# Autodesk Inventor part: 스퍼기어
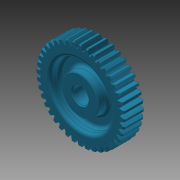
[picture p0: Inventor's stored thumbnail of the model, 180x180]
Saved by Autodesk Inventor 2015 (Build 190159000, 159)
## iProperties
Created: 2018-11
Part Number: 스퍼기어
Material: 알루미늄 6061
Document SubType Name: Modeling
Designer: mduedu
Categories: <?xml version="1.0" encoding="UTF-16"?> <MemberInstance><Categories><FamilyTemplate><FamilyTemplateParameter ValueType="xs:double" Id="1" ObjectReferenceKey="da
Density: 1 g/cm^3
Appearance: 터키옥색
CustomPartVersion: 1
Author: mduedu
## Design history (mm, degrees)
sketch "Sketch1"
  geometry: C1 r 42 at (0, 0)
  constraints: 1 centre point
  dimensions: "d0" = 83.99905 diameter of C1 (= da_da)
extrude "Extrusion1" new body sketch "Sketch1" distance "d1" = 19 (= da_b); taper "d2" = 0 deg
workplane "Work Plane2"
sketch "Sketch2"
  geometry: C1 r 42 at (0, 0) reference; C2 r 40.05 at (0, 0)
  constraints: 1 centre point, 1 coincident
  dimensions: "d3" = 80.10038 diameter of C2 (= da_dw)
feature "피치 지름" sketch "Sketch2" dims "d4" = 10, "d5" = 0
workplane "Work Plane8"
workplane "Work Plane9"
feature "스퍼 기어" dims "da_b" = 19, "da_d" = 80, "da_aw" = 80.10038, "da_da" = 83.99905, "da_df" = 75, "da_dw" = 80.10038, angle "da_beta" = 0 deg, "da_lefttooth" = 0, "da_righttooth" = 0
sketch "스케치3"
  geometry: L1 (-42, 19)-(42, 19) reference; L2 (42, 19)-(42, 0) reference; L3 (42, 0)-(-42, 0) reference; L4 (-42, 0)-(-42, 19) reference; L5 (0, 0)-(0, 19); L6 (42, 0)-(41, 0); L7 (42, 1)-(42, 0); L8 (42, 19)-(41, 19); L9 (42, 18)-(42, 19); L10 (41, 19)-(42, 18); L11 (41, 0)-(42, 1)
  constraints: 14 end point, 2 horizontal, 2 vertical, 1 midpoint
  dimensions: "d49" = 1 distance from line of L8.end L2; "d50" = 1 horizontal distance of L8.end L9.start; "d51" = 1 horizontal distance of L6.end L7.start; "d52" = 1 horizontal distance of L6.end L7.start
revolve "회전1" sketch "스케치3" stored, may be unused: angle "d53" = 90 deg
sketch "스케치4"
  geometry: L1 (-2.5, 7.071)-(2.5, 7.071); L2 (2.5, 7.071)-(2.5, 9.8); L3 (2.5, 9.8)-(-2.5, 9.8); L4 (-2.5, 9.8)-(-2.5, 7.071); A1 r 7.5 centre (0, 0) between (-2.5, 7.071) and (2.5, 7.071); 1 further point
  constraints: 8 end point, 2 parallel, 2 point on circle, 1 centre point, 1 coincident, 1 horizontal, 1 perpendicular
  dimensions: "d54" = 15 diameter of A1; "d56" = 17.3 dimension on A1 L3; "d57" = 5 distance of L2.end L3.end
extrude "돌출2" cut sketch "스케치4" stored distance "d58" = 10; taper "d59" = 0 deg
chamfer "모따기1" distance "d60" = 1; stored, may be unused: second distance "d61" = 2, angle "d62" = 45 deg
sketch "스케치5"
  geometry: C1 r 17.5 at (0, 0); C2 r 28.5 at (0, 0); 1 further point
  constraints: 2 centre point, 2 coincident
  dimensions: "d63" = 35 diameter of C1; "d64" = 57 diameter of C2
extrude "돌출3" cut sketch "스케치5" distance "d65" = 9.5; taper "d66" = 0 deg
fillet "모깎기1" dims "d67" = 3
chamfer "모따기2" distance "d68" = 0.5; stored, may be unused: second distance "d69" = 2, angle "d70" = 45 deg
body "Solid1"
body "Srf1"
node "절단 모서리 투영1"
other parameters: "d16" = 80.10038 (= da_aw), "d17" = 0, "d34" = 4.5 deg (computed from da_z), "d39" = 0, "d41" = 0, "d43" = 80.10038 (= da_aw), "d46" = 80.10038 (= da_aw), "d47" = 0, "d48" = 0
